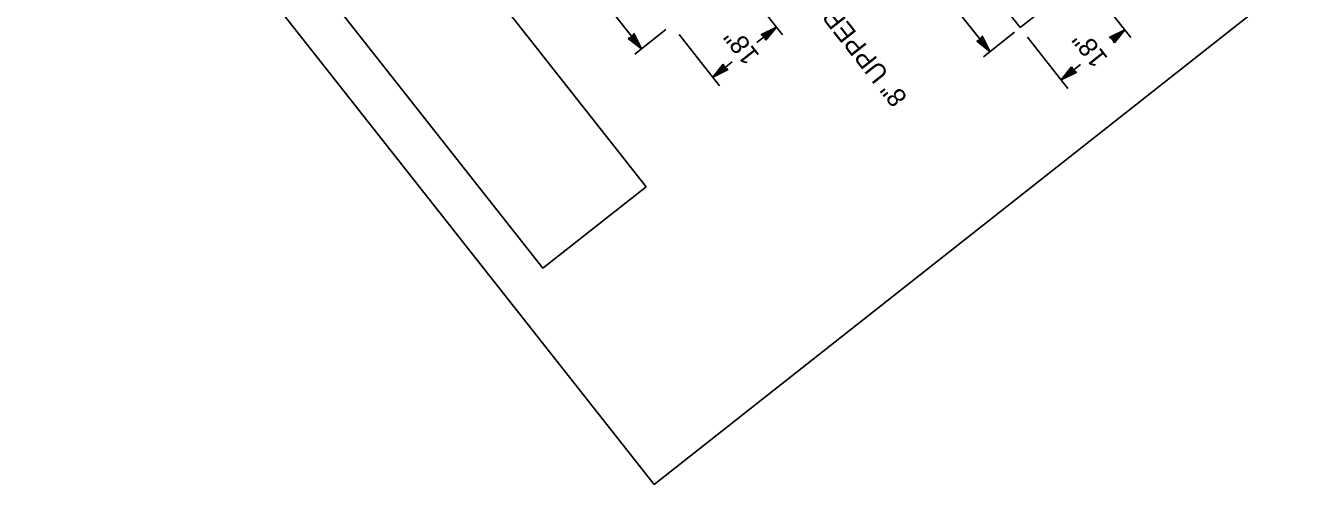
# Model space of a CAD drawing. Extents: x 672438 to 673980, y 1673259 to 1674850.
# Drawn here: x 673545.1 to 673827.5, y 1673259 to 1673361.1 of the extents above; entities that cross this region are included whole.
import ezdxf

# ---------------------------------------------------------------- set-up
doc = ezdxf.new("R2010")
doc.units = 0
for name, color, linetype in [('61', 7, 'Continuous'), ('C-ANNO-SYMB', 7, 'Continuous'), ('Level 1', 7, 'Continuous')]:
    doc.layers.add(name, color=color, linetype=linetype)

msp = doc.modelspace()

# ---------------------------------------------------------------- linework, layer by layer
at = {"layer": '61'}
msp.add_lwpolyline([(673683.11, 1673325.23), (673609.58, 1673418.5), (673586.62, 1673400.41), (673660.15, 1673307.14)], close=True, dxfattribs=at)
at = {"layer": 'C-ANNO-SYMB'}
for p, q in [((673688.27, 1673459.54), (673766.28, 1673360.6)), ((673766.28, 1673360.6), (673780.41, 1673371.74))]:
    msp.add_line(p, q, dxfattribs=at)
at = {"layer": 'Level 1'}
for p, q in [((673979.67, 1673491.41), (673684.88, 1673259.01)), ((673684.88, 1673259.01), (673545.09, 1673436.33)), ((673759.52, 1673355.27), (673726.64, 1673396.98)), ((673704.59, 1673370.18), (673713.42, 1673358.98)), ((673782.06, 1673369.59), (673790.89, 1673358.39)), ((673682.05, 1673355.86), (673673.67, 1673366.49)), ((673679.59, 1673358.16), (673680.29, 1673358.84)), ((673679.72, 1673358.3), (673680.29, 1673358.84)), ((673679.85, 1673358.5), (673680.33, 1673359.17)), ((673680.21, 1673358.82), (673680.4, 1673359.13)), ((673680.33, 1673359.17), (673680.26, 1673358.96)), ((673680.26, 1673358.96), (673680.36, 1673358.96)), ((673680.29, 1673358.84), (673681.31, 1673356.72)), ((673680.29, 1673358.84), (673681.44, 1673356.65)), ((673680.34, 1673359.32), (673682.05, 1673355.86)), ((673680.36, 1673358.96), (673681.78, 1673356.12)), ((673680.4, 1673359.13), (673681.69, 1673356.28)), ((673687.51, 1673360.16), (673680.6, 1673354.72)), ((673690.45, 1673359.04), (673699.41, 1673347.68)), ((673707.71, 1673357.3), (673712.05, 1673360.72)), ((673708.59, 1673359.01), (673712.05, 1673360.72)), ((673709.4, 1673358.52), (673708.73, 1673359)), ((673708.73, 1673359), (673708.95, 1673358.93)), ((673708.78, 1673359.07), (673711.63, 1673360.36)), ((673709.09, 1673358.88), (673708.78, 1673359.07)), ((673708.94, 1673359.03), (673711.79, 1673360.45)), ((673708.95, 1673358.93), (673708.94, 1673359.03)), ((673709.06, 1673358.96), (673711.26, 1673360.11)), ((673709.06, 1673358.96), (673711.19, 1673359.98)), ((673709.61, 1673358.39), (673709.06, 1673358.96)), ((673709.75, 1673358.26), (673709.06, 1673358.96)), ((673709.33, 1673358.57), (673709.09, 1673358.88)), ((673709.24, 1673358.9), (673710.75, 1673359.64)), ((673709.7, 1673358.39), (673709.24, 1673358.9)), ((673709.41, 1673358.86), (673710.37, 1673359.37)), ((673709.76, 1673358.54), (673709.41, 1673358.86)), ((673709.51, 1673358.81), (673710.03, 1673359.08)), ((673711.26, 1673360.11), (673709.7, 1673358.39)), ((673709.7, 1673358.52), (673710.21, 1673359.28)), ((673712.05, 1673360.72), (673709.73, 1673357.81)), ((673711.83, 1673360.48), (673709.74, 1673357.96)), ((673711.48, 1673360.21), (673709.75, 1673358.13)), ((673711.19, 1673359.98), (673709.75, 1673358.26)), ((673710.75, 1673359.64), (673709.76, 1673358.54)), ((673710.03, 1673359.08), (673709.76, 1673358.74)), ((673710.37, 1673359.37), (673709.79, 1673358.66)), ((673710.21, 1673359.28), (673710.46, 1673359.38)), ((673710.82, 1673359.73), (673710.39, 1673359.52)), ((673710.46, 1673359.38), (673710.82, 1673359.73)), ((673711.58, 1673360.42), (673710.78, 1673360)), ((673710.78, 1673360), (673711.48, 1673360.21)), ((673711.79, 1673360.45), (673711.58, 1673360.42)), ((673711.63, 1673360.36), (673711.83, 1673360.48)), ((673764.98, 1673359.57), (673758.08, 1673354.13)), ((673786.06, 1673358.42), (673789.52, 1673360.13)), ((673786.25, 1673358.48), (673789.1, 1673359.77)), ((673786.42, 1673358.44), (673789.26, 1673359.86)), ((673786.54, 1673358.37), (673788.73, 1673359.52)), ((673786.54, 1673358.37), (673788.66, 1673359.39)), ((673786.72, 1673358.31), (673788.23, 1673359.05)), ((673788.73, 1673359.52), (673787.18, 1673357.8)), ((673789.52, 1673360.13), (673787.2, 1673357.22)), ((673789.3, 1673359.89), (673787.22, 1673357.37)), ((673788.95, 1673359.62), (673787.22, 1673357.54)), ((673788.66, 1673359.39), (673787.22, 1673357.67)), ((673788.23, 1673359.05), (673787.23, 1673357.94)), ((673788.29, 1673359.14), (673787.86, 1673358.93)), ((673787.93, 1673358.79), (673788.29, 1673359.14)), ((673789.05, 1673359.83), (673788.25, 1673359.41)), ((673788.25, 1673359.41), (673788.95, 1673359.62)), ((673789.26, 1673359.86), (673789.05, 1673359.83)), ((673789.1, 1673359.77), (673789.3, 1673359.89)), ((673679.14, 1673358.18), (673679.9, 1673358.57)), ((673682.05, 1673355.86), (673679.14, 1673358.18)), ((673679.29, 1673358.16), (673679.85, 1673358.5)), ((673681.81, 1673356.08), (673679.29, 1673358.16)), ((673679.46, 1673358.16), (673679.72, 1673358.3)), ((673681.54, 1673356.43), (673679.46, 1673358.16)), ((673681.31, 1673356.72), (673679.59, 1673358.16)), ((673679.72, 1673358.2), (673680.23, 1673358.66)), ((673681.44, 1673356.65), (673679.72, 1673358.2)), ((673680.12, 1673358.58), (673679.85, 1673358.21)), ((673679.85, 1673358.21), (673680.61, 1673357.7)), ((673679.87, 1673358.15), (673680.19, 1673358.5)), ((673680.97, 1673357.15), (673679.87, 1673358.15)), ((673679.9, 1673358.57), (673680.21, 1673358.82)), ((673679.99, 1673358.11), (673680.14, 1673358.39)), ((673680.7, 1673357.54), (673679.99, 1673358.11)), ((673680.07, 1673358.14), (673680.13, 1673358.22)), ((673680.41, 1673357.88), (673680.07, 1673358.14)), ((673680.13, 1673358.22), (673680.12, 1673358.58)), ((673680.14, 1673358.39), (673680.41, 1673357.88)), ((673680.19, 1673358.5), (673680.7, 1673357.54)), ((673680.23, 1673358.66), (673680.97, 1673357.15)), ((673680.61, 1673357.7), (673680.71, 1673357.45)), ((673680.71, 1673357.45), (673681.06, 1673357.09)), ((673681.06, 1673357.09), (673680.85, 1673357.52)), ((673681.75, 1673356.33), (673681.33, 1673357.13)), ((673681.33, 1673357.13), (673681.54, 1673356.43)), ((673681.69, 1673356.28), (673681.81, 1673356.08)), ((673681.78, 1673356.12), (673681.75, 1673356.33)), ((673709.68, 1673358.81), (673709.33, 1673358.79)), ((673709.33, 1673358.79), (673709.7, 1673358.52)), ((673709.73, 1673357.81), (673709.33, 1673358.57)), ((673709.74, 1673357.96), (673709.4, 1673358.52)), ((673709.79, 1673358.66), (673709.51, 1673358.81)), ((673709.75, 1673358.13), (673709.61, 1673358.39)), ((673709.76, 1673358.74), (673709.68, 1673358.81)), ((673756.61, 1673357.59), (673757.37, 1673357.98)), ((673759.52, 1673355.27), (673756.61, 1673357.59)), ((673756.76, 1673357.57), (673757.33, 1673357.91)), ((673759.28, 1673355.49), (673756.76, 1673357.57)), ((673756.93, 1673357.57), (673757.19, 1673357.71)), ((673759.01, 1673355.84), (673756.93, 1673357.57)), ((673757.06, 1673357.57), (673757.76, 1673358.25)), ((673758.79, 1673356.13), (673757.06, 1673357.57)), ((673757.19, 1673357.71), (673757.76, 1673358.25)), ((673757.19, 1673357.61), (673757.7, 1673358.07)), ((673758.91, 1673356.06), (673757.19, 1673357.61)), ((673757.33, 1673357.91), (673757.8, 1673358.58)), ((673757.6, 1673357.99), (673757.33, 1673357.62)), ((673757.33, 1673357.62), (673758.08, 1673357.11)), ((673757.34, 1673357.56), (673757.66, 1673357.91)), ((673758.45, 1673356.56), (673757.34, 1673357.56)), ((673757.37, 1673357.98), (673757.68, 1673358.22)), ((673757.46, 1673357.52), (673757.61, 1673357.8)), ((673758.18, 1673356.95), (673757.46, 1673357.52)), ((673757.54, 1673357.55), (673757.61, 1673357.63)), ((673757.88, 1673357.29), (673757.54, 1673357.55)), ((673757.61, 1673357.63), (673757.6, 1673357.99)), ((673757.61, 1673357.8), (673757.88, 1673357.29)), ((673757.66, 1673357.91), (673758.18, 1673356.95)), ((673757.68, 1673358.22), (673757.87, 1673358.54)), ((673757.7, 1673358.07), (673758.45, 1673356.56)), ((673757.8, 1673358.58), (673757.73, 1673358.36)), ((673757.73, 1673358.36), (673757.83, 1673358.37)), ((673757.76, 1673358.25), (673758.79, 1673356.13)), ((673757.76, 1673358.25), (673758.91, 1673356.06)), ((673757.82, 1673358.73), (673759.52, 1673355.27)), ((673757.83, 1673358.37), (673759.25, 1673355.53)), ((673757.87, 1673358.54), (673759.16, 1673355.69)), ((673758.08, 1673357.11), (673758.18, 1673356.86)), ((673758.18, 1673356.86), (673758.53, 1673356.49)), ((673758.53, 1673356.49), (673758.32, 1673356.93)), ((673759.22, 1673355.74), (673758.8, 1673356.54)), ((673758.8, 1673356.54), (673759.01, 1673355.84)), ((673767.92, 1673358.45), (673776.88, 1673347.09)), ((673786.88, 1673357.93), (673786.21, 1673358.41)), ((673786.21, 1673358.41), (673786.42, 1673358.34)), ((673786.57, 1673358.29), (673786.25, 1673358.48)), ((673786.42, 1673358.34), (673786.42, 1673358.44)), ((673787.08, 1673357.8), (673786.54, 1673358.37)), ((673787.22, 1673357.67), (673786.54, 1673358.37)), ((673786.81, 1673357.98), (673786.57, 1673358.29)), ((673787.18, 1673357.8), (673786.72, 1673358.31)), ((673787.16, 1673358.21), (673786.8, 1673358.2)), ((673786.8, 1673358.2), (673787.17, 1673357.93)), ((673787.2, 1673357.22), (673786.81, 1673357.98)), ((673786.88, 1673358.27), (673787.84, 1673358.78)), ((673787.23, 1673357.94), (673786.88, 1673358.27)), ((673787.22, 1673357.37), (673786.88, 1673357.93)), ((673786.99, 1673358.22), (673787.5, 1673358.49)), ((673787.27, 1673358.07), (673786.99, 1673358.22)), ((673787.22, 1673357.54), (673787.08, 1673357.8)), ((673787.24, 1673358.15), (673787.16, 1673358.21)), ((673787.17, 1673357.93), (673787.68, 1673358.69)), ((673787.5, 1673358.49), (673787.24, 1673358.15)), ((673787.84, 1673358.78), (673787.27, 1673358.07)), ((673787.68, 1673358.69), (673787.93, 1673358.79)), ((673759.16, 1673355.69), (673759.28, 1673355.49)), ((673759.25, 1673355.53), (673759.22, 1673355.74)), ((673697.91, 1673349.57), (673702.24, 1673352.98)), ((673697.91, 1673349.57), (673700.23, 1673352.48)), ((673701.37, 1673351.28), (673697.91, 1673349.57)), ((673698.13, 1673349.81), (673700.21, 1673352.33)), ((673701.02, 1673351.26), (673698.17, 1673349.84)), ((673701.18, 1673351.23), (673698.33, 1673349.93)), ((673698.48, 1673350.09), (673700.21, 1673352.17)), ((673698.7, 1673350.19), (673700.25, 1673351.9)), ((673700.89, 1673351.34), (673698.7, 1673350.19)), ((673698.77, 1673350.31), (673700.21, 1673352.03)), ((673700.89, 1673351.34), (673698.77, 1673350.31)), ((673699.5, 1673350.91), (673699.14, 1673350.56)), ((673699.14, 1673350.56), (673699.57, 1673350.77)), ((673699.21, 1673350.65), (673700.2, 1673351.76)), ((673700.72, 1673351.39), (673699.21, 1673350.65)), ((673699.75, 1673351.01), (673699.5, 1673350.91)), ((673699.59, 1673350.92), (673700.16, 1673351.63)), ((673700.55, 1673351.43), (673699.59, 1673350.92)), ((673700.26, 1673351.77), (673699.75, 1673351.01)), ((673699.93, 1673351.21), (673700.19, 1673351.55)), ((673700.45, 1673351.48), (673699.93, 1673351.21)), ((673700.16, 1673351.63), (673700.45, 1673351.48)), ((673700.19, 1673351.55), (673700.28, 1673351.49)), ((673700.2, 1673351.76), (673700.55, 1673351.43)), ((673700.21, 1673352.33), (673700.56, 1673351.77)), ((673700.21, 1673352.17), (673700.35, 1673351.91)), ((673700.21, 1673352.03), (673700.89, 1673351.34)), ((673700.23, 1673352.48), (673700.63, 1673351.72)), ((673700.25, 1673351.9), (673700.72, 1673351.39)), ((673700.63, 1673351.5), (673700.26, 1673351.77)), ((673700.28, 1673351.49), (673700.63, 1673351.5)), ((673700.35, 1673351.91), (673700.89, 1673351.34)), ((673700.56, 1673351.77), (673701.23, 1673351.3)), ((673700.63, 1673351.72), (673700.87, 1673351.41)), ((673700.87, 1673351.41), (673701.18, 1673351.23)), ((673701.23, 1673351.3), (673701.01, 1673351.36)), ((673701.01, 1673351.36), (673701.02, 1673351.26)), ((673775.38, 1673348.98), (673779.71, 1673352.39)), ((673775.38, 1673348.98), (673777.71, 1673351.89)), ((673778.85, 1673350.69), (673775.38, 1673348.98)), ((673775.6, 1673349.22), (673777.69, 1673351.74)), ((673778.49, 1673350.67), (673775.64, 1673349.25)), ((673778.65, 1673350.63), (673775.81, 1673349.34)), ((673775.95, 1673349.49), (673777.68, 1673351.57)), ((673776.17, 1673349.59), (673777.73, 1673351.31)), ((673778.37, 1673350.74), (673776.17, 1673349.59)), ((673776.24, 1673349.72), (673777.69, 1673351.44)), ((673778.37, 1673350.74), (673776.24, 1673349.72)), ((673776.68, 1673350.06), (673777.67, 1673351.17)), ((673778.19, 1673350.8), (673776.68, 1673350.06)), ((673777.22, 1673350.42), (673776.97, 1673350.32)), ((673777.07, 1673350.33), (673777.64, 1673351.04)), ((673778.03, 1673350.84), (673777.07, 1673350.33)), ((673777.73, 1673351.18), (673777.22, 1673350.42)), ((673777.4, 1673350.62), (673777.67, 1673350.96)), ((673777.92, 1673350.89), (673777.4, 1673350.62)), ((673777.64, 1673351.04), (673777.92, 1673350.89)), ((673777.67, 1673351.17), (673778.03, 1673350.84)), ((673777.67, 1673350.96), (673777.75, 1673350.9)), ((673777.68, 1673351.57), (673777.82, 1673351.31)), ((673777.69, 1673351.74), (673778.03, 1673351.18)), ((673777.69, 1673351.44), (673778.37, 1673350.74)), ((673777.71, 1673351.89), (673778.1, 1673351.13)), ((673777.73, 1673351.31), (673778.19, 1673350.8)), ((673778.11, 1673350.91), (673777.73, 1673351.18)), ((673777.75, 1673350.9), (673778.11, 1673350.91)), ((673777.82, 1673351.31), (673778.37, 1673350.74)), ((673778.03, 1673351.18), (673778.7, 1673350.7)), ((673778.1, 1673351.13), (673778.34, 1673350.82)), ((673778.34, 1673350.82), (673778.65, 1673350.63)), ((673778.7, 1673350.7), (673778.48, 1673350.77)), ((673778.48, 1673350.77), (673778.49, 1673350.67)), ((673698.33, 1673349.93), (673698.13, 1673349.81)), ((673698.17, 1673349.84), (673698.38, 1673349.87)), ((673698.38, 1673349.87), (673699.18, 1673350.3)), ((673699.18, 1673350.3), (673698.48, 1673350.09)), ((673775.81, 1673349.34), (673775.6, 1673349.22)), ((673775.64, 1673349.25), (673775.85, 1673349.28)), ((673775.85, 1673349.28), (673776.65, 1673349.71)), ((673776.65, 1673349.71), (673775.95, 1673349.49)), ((673776.97, 1673350.32), (673776.61, 1673349.97)), ((673776.61, 1673349.97), (673777.05, 1673350.18))]:
    msp.add_line(p, q, dxfattribs=at)

# ---------------------------------------------------------------- texts
for s, p in [('8" UPPERCASE', (673741.35, 1673345.1)), ('18"', (673708.46, 1673354.41)), ('18"', (673785.93, 1673353.82))]:
    msp.add_text(s, height=4.2, rotation=128.2505, dxfattribs=at).set_placement(p)

doc.saveas('drawing.dxf')
